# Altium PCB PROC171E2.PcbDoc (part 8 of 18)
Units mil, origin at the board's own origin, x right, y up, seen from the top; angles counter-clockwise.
Board outline 7700 x 2300 mil, 6 copper layers (Top Layer, GND 1, SIG 1, SIG 2, GND 2, Bottom Layer), stack 61.062 mil thick; 937 components, 687 nets, 11931 pads, 1719 vias.
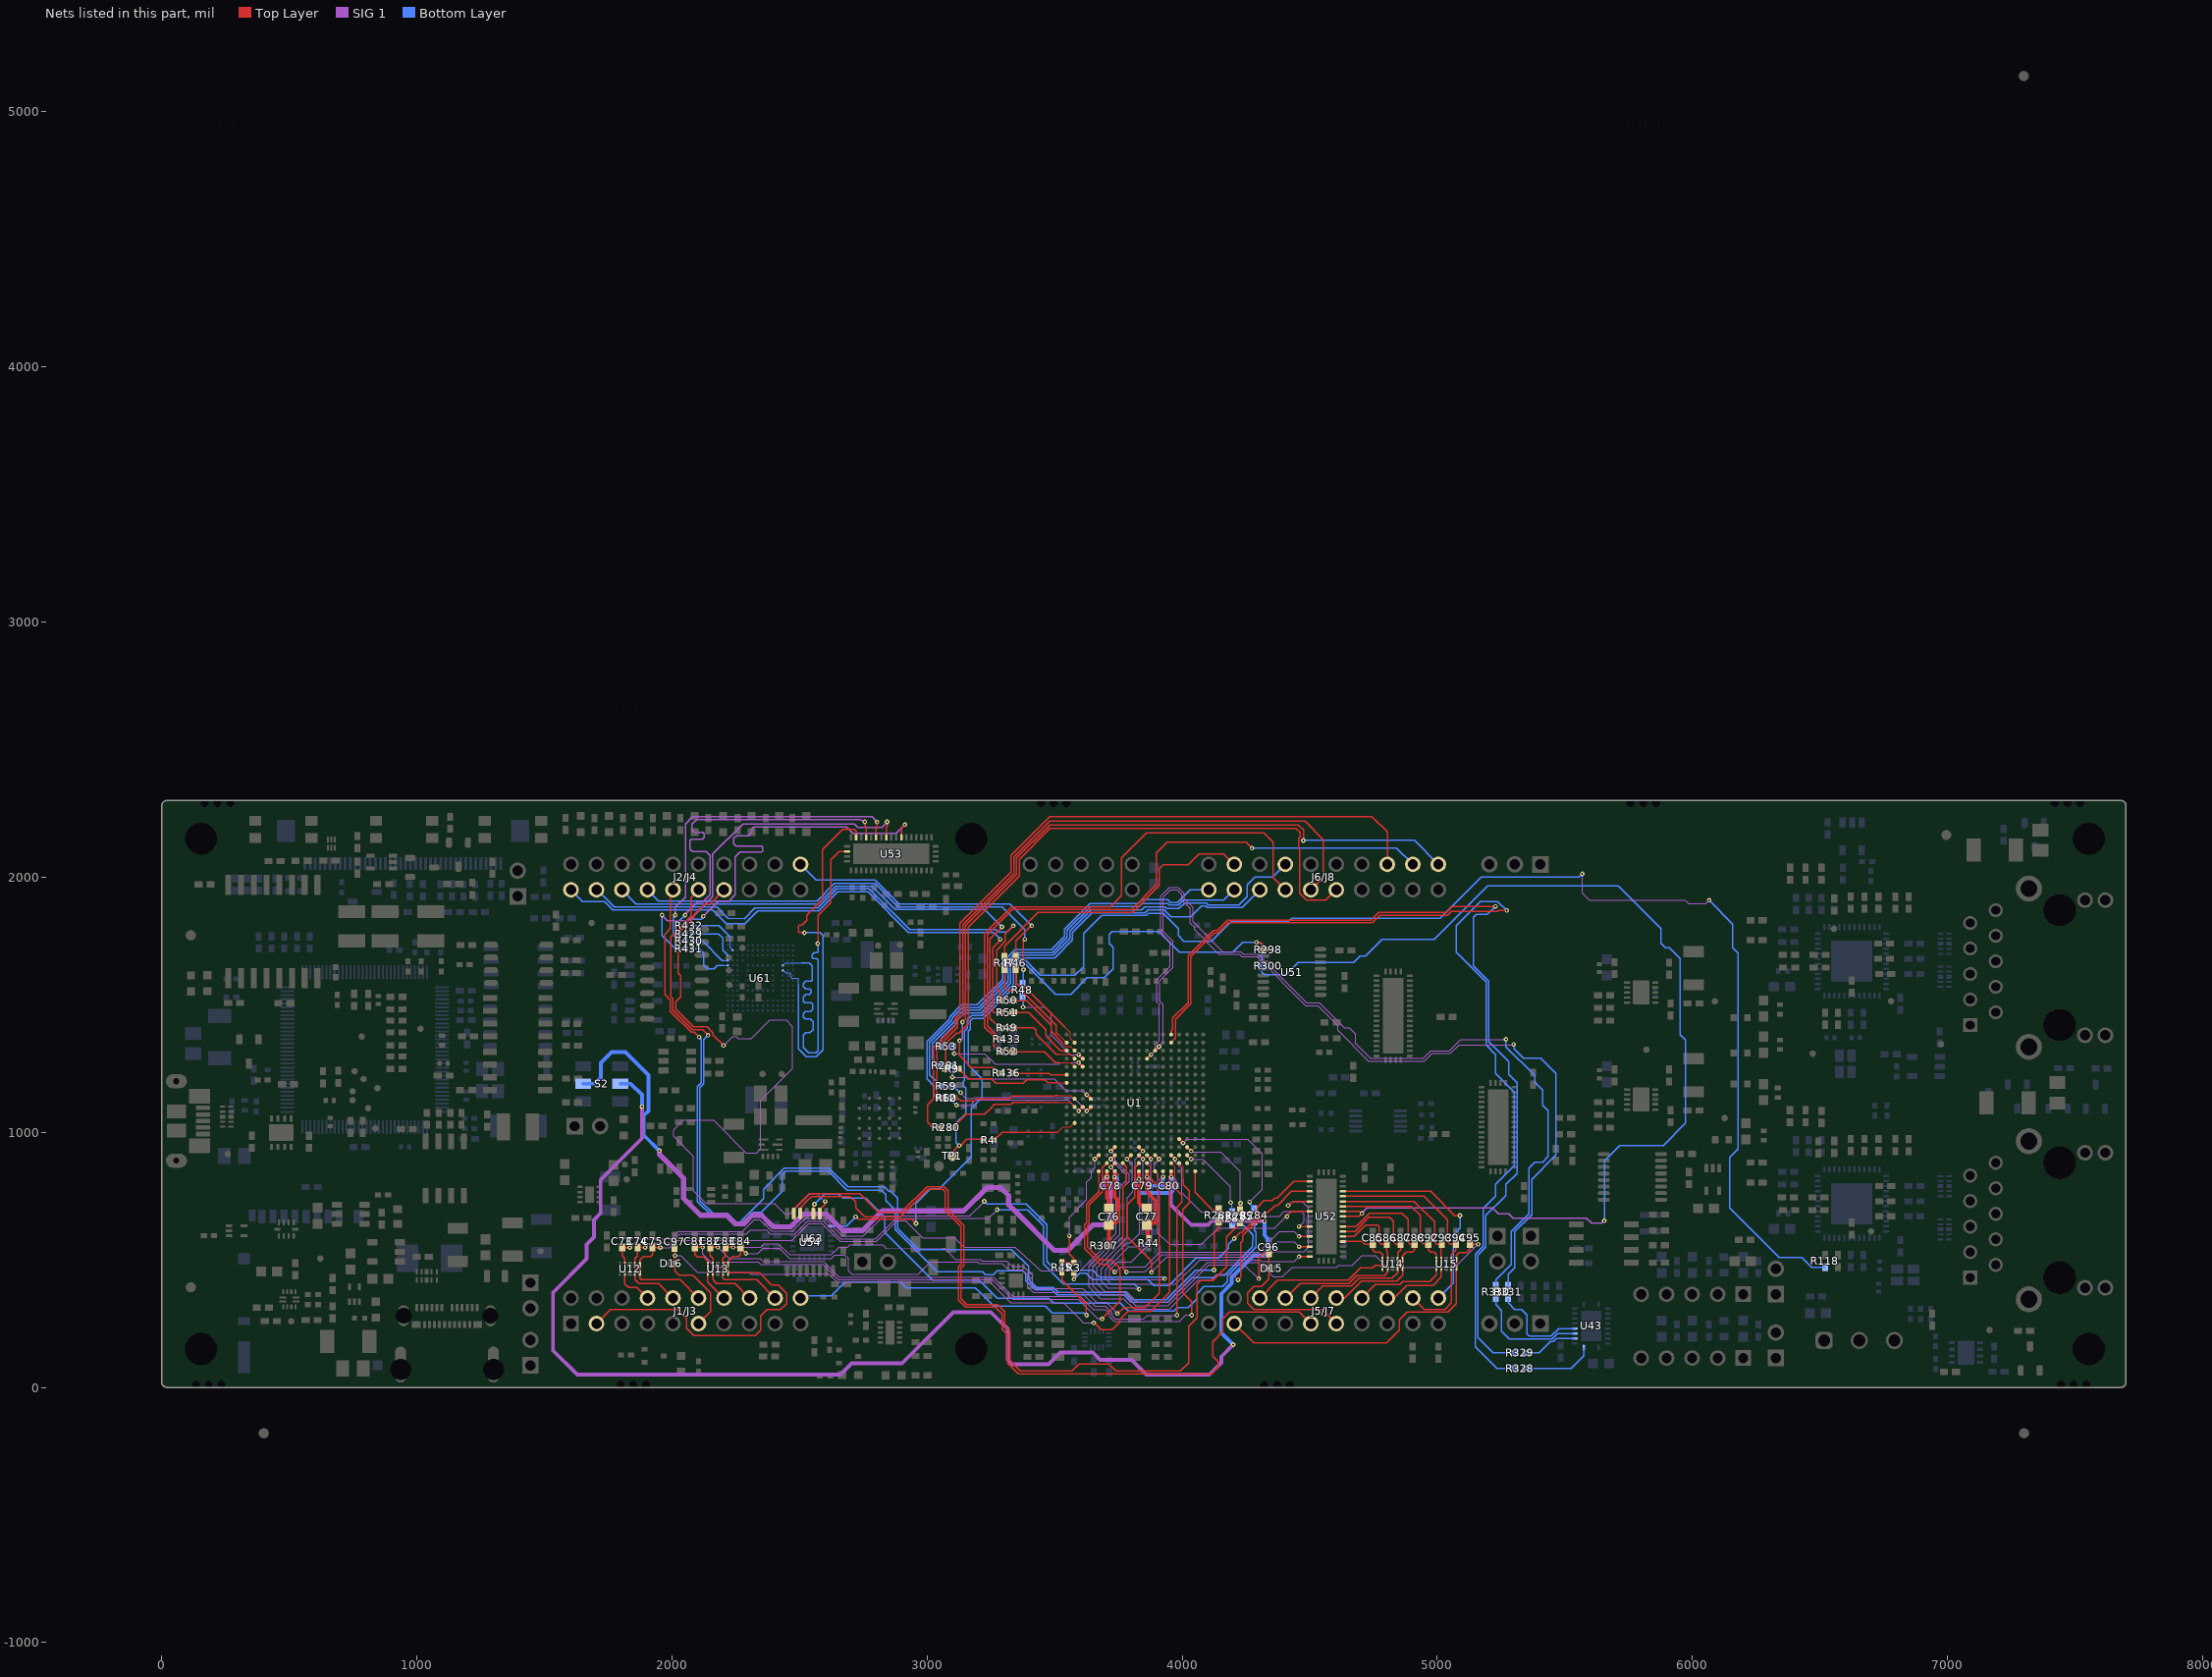
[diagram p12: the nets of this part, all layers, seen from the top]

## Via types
v1: diameter 18, hole 8, Top Layer to Bottom Layer, tented both sides, 1588 vias
v2: diameter 19.68, hole 7.87, Top Layer to Bottom Layer, tented both sides, 104 vias
v3: diameter 19.68, hole 7.87, Top Layer to Bottom Layer, 24 vias
v4: diameter 18, hole 8, Top Layer to Bottom Layer, 3 vias

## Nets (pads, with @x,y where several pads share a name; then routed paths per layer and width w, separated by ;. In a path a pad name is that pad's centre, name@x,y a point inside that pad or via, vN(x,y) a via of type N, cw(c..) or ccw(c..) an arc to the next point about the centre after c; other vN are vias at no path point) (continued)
AM263P_ADC0_AIN1: C82.1 J1/J3.28 U1.U15 U13.2 U13.9 | length 2968.2
  Top Layer w4: U1.U15@3988.08,878.86 4003.83,863.11 4003.83,815.87
  Top Layer w5.3: v1@2180,548.85 C82.1@2150,548.85 2150,516.35 2160.31,506.03 U13.9@2160.31,481.44 U13.2@2160.31,448.56 2160.31,421.62 2175,406.94 2247.24,406.94 J1/J3.28@2304.17,350 ; 4003.98,815.87 4003.98,794.2 4028.17,770.01 4028.17,723.29 4003.3,698.42 4003.3,371.19 4022.49,352.01 ; 4022.59,352.1 4037.98,336.71 4037.98,283.66 v1(4037.09,282.77)
  SIG 1 w4.75: v1(2180,548.85) 2223.8,505.05 2346.24,505.05 2357.98,493.31 2594.84,493.31 2655.35,432.81 3259.9,432.81 3335.06,357.65 3599.47,357.65 3652.12,305 3698.67,305 3716.12,287.55 3716.12,275.55 3733.57,258.1 3989.19,258.1 4014.75,283.66 4036.2,283.66 v1(4037.09,282.77)
AM263P_ADC0_AIN2: U1.T14 U52.32 | length 790.2
  Top Layer w5.3: v1(4458.39,630.63) U52.32@4500.04,630.63
  Top Layer w10: U1.T14@3956.58,910.35 v1(3972.33,894.61)
  SIG 1 w4.75: v1(3972.33,894.61) 3972.33,885.08 3999.43,857.98 3999.43,762.5 4073.08,688.86 4305.29,688.86 4323.32,670.83 4381.38,670.83 4399.8,689.25 4465.75,689.25 4477.03,677.97 4477.03,649.27 v1(4458.39,630.63)
AM263P_ADC0_AIN2_LIN1_TXD: C88.1 J5/J7.66 U14.5 U14.6 U52.7 | length 857.5
  Top Layer w5.3: J5/J7.66@4604.17,350 4635.87,350 4703.06,417.19 4841.67,417.19 4864.37,439.89 U14.5@4864.37,467.68 U14.6@4864.37,500.55 4864.37,516.12 4877.56,529.31 4902.1,529.31 4910,537.21 4910,560.42 C88.1@4911.11,561.53 4893.47,561.53 4885,570 4885,658.91 4861.58,682.33 4734.12,682.33 4682.42,630.63 U52.7@4629.96,630.63
AM263P_ADC0_AIN3: C84.1 J1/J3.2 U1.U14 U13.5 U13.6 | length 3940.1
  Top Layer w4: U1.U14@3956.58,878.86 3972.4,863.04 3972.4,816.09 3972.18,815.87
  Top Layer w5.3: J1/J3.2@1704.17,250 1759.17,305 2022.85,305 2057.7,270.15 2057.7,231.07 2085.4,203.37 2327.15,203.37 2348.22,224.45 2348.22,280.88 2372.23,304.88 2424.91,304.88 2449.05,329.02 2449.05,368.8 2416.56,401.3 2390.74,401.3 2343.48,448.56 U13.5@2219.37,448.56 U13.6@2219.37,481.44 2219.37,494.53 2238.22,513.38 2261.62,513.38 2269,520.76 C84.1@2269,544.91 ; C84.1@2269,548.85 C84.1@2269,544.91 ; v1(2289.41,525.59) 2288.33,525.59 C84.1@2269,544.91 ; 3972.18,815.87 3972.18,780.46 3999.52,753.11 3999.52,725.47 3979.46,705.41 v1(3979.46,282.66)
  SIG 1 w4.75: v1(2289.41,525.59) 2290.99,524.01 2336.11,524.01 2357.35,545.25 2420.66,545.25 2460.77,505.14 2623.82,505.14 2628.28,509.59 2638.22,519.49 2677.05,519.49 2691.97,504.56 2691.97,456.29 2705.41,442.86 2964.9,442.86 3013.89,491.85 3198.05,491.85 3203.71,486.19 3293.81,486.19 3319.1,460.9 3371.67,460.9 3395,437.57 3395,392.52 3415.02,372.5 3604.77,372.5 3658.02,319.25 3698.63,319.25 3726.17,291.71 3726.17,279.72 3737.74,268.15 3849.55,268.15 3864.06,282.66 v1(3979.46,282.66)
AM263P_ADC1_AIN0: C73.1 J1/J3.24 U1.T11 U12.2 U12.9 | length 3570.9
  Top Layer w5.3: v1(1835,548.33) C73.1@1805,548.33 1805,515.82 1815.31,505.51 1815.31,405.72 1830,391.04 1863.14,391.04 J1/J3.24@1904.17,350
  Top Layer w10: U1.T11@3862.09,910.35 v1(3877.84,894.61)
  SIG 1 w4.75: v1(1835,548.33) 1868.5,581.83 1994.64,581.83 2024.06,611.25 2276.97,611.25 2322.58,656.86 2344.56,656.86 2389.37,612.05 2472.24,612.05 2522.24,662.05 2597.23,662.05 2666.22,593.06 2750.82,593.06 2830.68,672.92 3168.08,672.92 v1(3224.39,729.23) ; v1(3877.84,894.61) 3877.84,813.9 3881.31,810.44 3881.31,571.58 3801.23,491.5 3747.49,491.5 3717.5,461.51 3717.5,460.9 3716.29,459.69 3716.29,434.28 3728.62,421.95 3928.63,421.95 v1@3931.68,425
  Bottom Layer w5.3: v1(3224.39,729.23) 3234.54,719.08 3389.14,719.08 3469.57,638.65 3469.57,493.7 3504.61,458.66 3649.62,458.66 3675.73,432.55 3870.69,432.55 3871.91,431.33 3922.81,431.33 3928.24,425.89 v1(3931.68,425.89)
AM263P_ADC1_AIN1: C83.1 J1/J3.29 U1.U11 U13.4 U13.7 | length 2801.4
  Top Layer w4: U1.U11@3862.09,878.86 3877.84,863.11 3877.84,818.36 3880.34,815.87
  Top Layer w5.3: v1@2240,548.85 C83.1@2210,548.85 2210,515.31 2199.68,505 U13.7@2199.68,481.44 U13.4@2199.68,448.56 2199.68,428.15 2205,422.84 2331.34,422.84 J1/J3.29@2404.17,350 ; v1(3745.71,289.03) 3747.34,289.03 3770.92,312.6 3854.57,312.6 3909.82,367.86 3909.82,639.65 3910.38,640.21 3910.38,785.82 3880.34,815.87
  SIG 1 w4.75: v1(2240,548.85) 2346.74,548.85 2361.27,563.38 2416.74,563.38 2460.48,519.64 2624.16,519.64 2652.71,548.19 2654.1,549.58 2687.53,549.99 ccw(c2687.48,554.74) 2690.84,551.38 2698.05,558.6 2825.99,558.6 2840.59,544 3064.19,546.12 3068.13,546.12 3069.52,544.73 3112.34,501.9 3209.15,501.9 3214.81,496.24 3311.61,496.24 3332.7,475.15 3377.57,475.15 3413.27,439.45 3413.27,400.89 3426.5,387.66 3610.31,387.66 3664.47,333.5 3702.71,333.5 3745.71,290.5 v1(3745.71,289.03)
AM263P_ADC1_AIN2: U1.T12 U52.29 | length 995.1
  Top Layer w5.3: v1(4411.13,670) 4411.13,673.36 4427.46,689.69 U52.29@4500.04,689.68
  Top Layer w10: U1.T12@3893.59,910.35 v1(3909.34,894.61)
  SIG 1 w4: 3890.46,850 3890.46,874.7 3909.34,893.58 v1(3909.34,894.61)
  SIG 1 w4.75: 3890.46,850 3904.9,835.56 3904.9,605 3949.9,560 4075.6,560 4140.36,624.76 4362.54,624.76 4407.78,670 v1(4411.13,670)
AM263P_ADC1_AIN2_SDFM0_D2: C92.1 J5/J7.67 U15.1 U15.10 U52.11 | length 926.3
  Top Layer w5.3: U52.11@4629.96,709.37 4897.79,709.37 4933.44,673.72 4933.44,574.11 4945.18,562.38 C92.1@4965,562.38 4965,540 4975,530 4988.59,530 4996.03,522.56 U15.10@4996.03,500.69 U15.1@4996.03,467.82 4996.03,440.53 4970.21,414.7 4865.21,414.7 4852.93,402.43 4756.6,402.43 J5/J7.67@4704.17,350
AM263P_ADC1_AIN3: C97.1 D16.1 J1/J3.6 U1.V12 | length 3035.3
  Top Layer w4: U1.V12@3893.59,847.36 3905,835.95 3905,822.02 3911.16,815.87
  Top Layer w5.3: C97.1@2010,547.76 2011.57,546.19 v1(2011.57,516.57) 2011.04,516.04 2011.04,490.55 2010.51,490.03 2010.51,457.6 2028.08,440.03 2082.25,440.03 2151,371.28 2151,296.83 J1/J3.6@2104.17,250 ; v1(3653.66,252.52) 3655.84,252.52 3682.98,225.39 3724.72,225.39 3754.74,255.41 3754.74,264.98 3787.78,298.02 3876.43,298.02 3951.58,373.17 3951.58,775.44 3911.16,815.87
  SIG 1 w4.75: v1(2011.57,516.57) 2034.76,516.57 2099.66,451.68 2302.03,451.68 2309.45,444.26 2460.97,444.26 2462.46,445.76 2613.97,445.76 2647.02,412.71 3247,412.71 3327.71,332 3534.6,332 3595.72,270.88 3595.72,270.44 3612.88,253.28 3652.9,253.28 v1(3653.66,252.52)
AM263P_ADC2_AIN0: C74.1 J1/J3.25 U1.R10 U12.4 U12.7 | length 3407.6
  Top Layer w5.3: v1(1895,548.33) C74.1@1865,548.33 1865,514.79 1854.68,504.48 U12.7@1854.68,480.91 U12.4@1854.68,448.04 1854.68,422.25 1870,406.94 1947.24,406.94 J1/J3.25@2004.17,350
  Top Layer w10: U1.R10@3830.6,941.85 v1(3846.35,926.1)
  SIG 1 w4.75: v1(1895,548.33) 1914.25,567.58 1995.86,567.58 2029.49,601.2 2291.98,601.2 2307.39,616.62 2370.59,616.62 2385.21,602 2481.74,602 2531.74,652 2593.07,652 2606.85,638.22 2662.06,583.01 2797.84,583.01 2818.52,603.69 2818.57,603.74 2879.32,662.87 3241.32,662.87 v1(3274.95,696.5) ; v1(3831.58,385.13) 3817.01,385.13 3811.63,390.5 3708.44,390.5 3682.23,416.7 3682.23,464.48 3783.89,566.14 3796.1,566.14 3832.75,602.79 3832.75,778.4 3815,796.15 3815,894.76 v1(3846.35,926.1)
  Bottom Layer w5.3: v1(3274.95,696.5) 3393.99,696.5 3455.71,634.78 3455.71,484.14 3535.57,404.28 3812.43,404.28 v1(3831.58,385.13)
AM263P_ADC2_AIN1: U1.T10 U52.38 | length 1460.2
  Top Layer w5.3: v1(4458.39,512.52) U52.38@4500.04,512.52
  Top Layer w10: U1.T10@3830.6,910.35 v1(3846.35,894.61)
  SIG 1 w4: v1(3846.35,894.61) 3847,893.95 3847,815.87
  SIG 1 w4.75: 3847,815.87 3847,799.35 3870.75,775.6 3870.75,579.71 3842.93,551.89 3791.41,551.89 3700.43,460.9 3700.43,426.71 3722.38,404.75 3825.52,404.75 3825.89,404.38 3973.87,404.38 4069.46,499.96 4303.16,499.96 4309.85,493.27 4439.14,493.27 v1(4458.39,512.52)
AM263P_ADC2_AIN1_MCAN5_RX: C85.1 J5/J7.63 U14.1 U14.10 U52.4 | length 781.9
  Top Layer w5.3: J5/J7.63@4304.17,350 4374.17,420 4650.72,420 4698.4,467.68 4746.98,467.68 4756.74,477.44 4772.92,477.44 4774.55,475.8 4784.34,475.8 4784.34,468.97 U14.1@4785.63,467.68 ; U52.4@4629.96,571.57 4705.59,571.57 4715.63,561.53 C85.1@4747.11,561.53 4747.11,538.93 4755.01,531.03 4774.59,531.03 4785.63,519.99 U14.10@4785.63,500.55 U14.1@4785.63,470.66
AM263P_ADC2_AIN2: U1.U10 U52.27 | length 1484.3
  Top Layer w5.3: U1.U10@3830.6,878.86 3813.63,861.89 3813.63,815.87 3813.63,745.2 3785.48,717.06 3785.48,589.52 3880,495 v1(3880,450.85) ; v1(4415.63,712.91) 4416.63,712.91 4432.77,729.06 U52.27@4500.04,729.06
  SIG 1 w4.75: v1(3880,450.85) 3939.16,510.01 4335.27,510.01 4357.02,531.77 4477.64,531.77 4495.75,549.88 4495.75,703.31 4470,729.06 4432.77,729.06 4429.21,725.5 v1(4415.63,712.91)
AM263P_ADC2_AIN2_SDFM0_CLK2: C93.1 J5/J7.68 U15.2 U15.9 U52.12 | length 879.5
  Top Layer w5.3: U52.12@4629.96,729.06 4909.46,729.06 4990,648.51 4990,570 4998.33,561.67 C93.1@5017.97,561.67 5015.48,559.18 5015.48,500.94 U15.9@5015.72,500.69 U15.2@5015.72,467.82 5015.72,432.26 4983.46,400 4879.37,400 4829.37,350 J5/J7.68@4804.17,350
AM263P_ADC2_AIN3: C95.1 J5/J7.42 U1.T9 U15.5 U15.6 | length 3575.6
  Top Layer w5.3: J5/J7.42@4204.17,250 4280.97,173.2 4801.74,173.2 4852.06,223.52 4852.06,265 4881.8,294.74 5041.07,294.74 5074.77,328.45 U15.5@5074.77,467.82 U15.6@5074.77,500.69 5074.77,517.29 5085.81,528.33 5114.41,528.33 5128.54,542.46 C95.1@5128.54,561.67 5144.64,561.67 v1(5159.85,561.03)
  Top Layer w10: v1(3783.35,894.61) U1.T9@3799.1,910.35
  SIG 1 w4.75: v1(3783.35,894.61) 3804.95,873.01 3804.95,791.99 3806.82,790.12 3806.82,766.43 3785,744.61 3785,587.4 3665.68,468.08 3665.68,406.97 3696.4,376.25 3781.88,376.25 3823.5,334.63 3943.14,334.63 4098.43,489.91 4299,489.91 4355.75,433.16 4393.5,433.16 4431.09,470.75 4604.29,470.75 4611.68,478.14 4666.51,478.14 4704.94,516.57 4756.24,516.57 4802.06,470.75 5069.57,470.75 v1(5159.85,561.03)
AM263P_ADC3_AIN0: C75.1 J1/J3.26 U1.U7 U12.5 U12.6 | length 2776.5
  Top Layer w5.3: v1(1954,548.33) C75.1@1924,548.33 1924,520.24 1916.62,512.86 1887.02,512.86 1874.37,500.2 U12.6@1874.37,480.91 U12.5@1874.37,448.04 1874.37,428.47 1880,422.84 2031.34,422.84 J1/J3.26@2104.17,350
  Top Layer w10: v1(3720.36,863.11) U1.U7@3736.11,878.86
  SIG 1 w4: v1@3720.36,862.49 v1(3720.36,863.11)
  SIG 1 w4.75: v1(1954,548.33) 1990.82,548.33 2017.38,574.89 2018.77,576.28 2022.71,576.28 2324.7,576.22 2470.17,576.22 2535.9,641.95 2588.9,641.95 2596.8,634.06 2659.07,571.78 2802.45,571.78 2883.49,652.82 2914.87,652.82 2982.68,585.01 3108.65,585.01 3143.55,550.11 3344.44,550.11 3447.34,457.66 3600.73,457.66 3695.11,552.04 3741.83,604.69 3741.83,786.42 3750.08,794.67 3750.08,832.77 v1@3720.36,862.49
AM263P_ADC3_AIN1: U1.U8 U52.36 | length 1219.8
  Top Layer w5.3: U1.U8@3767.61,878.86 3782.13,864.33 3782.13,815.87 3782.13,798.59 3768.05,784.5 3768.05,465.99 3781.85,452.18 v1(3781.85,452.07) ; v1(4458.39,551.89) U52.36@4500.04,551.89
  SIG 1 w4.75: v1(3781.85,452.07) 3782.53,452.75 3854.68,452.75 3921.99,520.06 4320.06,520.06 4371.14,571.14 4439.14,571.14 v1(4458.39,551.89)
AM263P_ADC3_AIN1_MCAN5_TX: C86.1 J5/J7.64 U14.2 U14.9 U52.5 | length 812.1
  Top Layer w5.3: J5/J7.64@4404.17,350 4462.03,407.86 4653.57,407.86 4684.1,438.39 4792.53,438.39 4805.31,451.17 U14.2@4805.31,467.68 U14.9@4805.31,500.55 4805.31,533.2 4802.11,536.4 C86.1@4802.11,561.53 4780.42,561.53 4772.38,569.58 4772.38,630 4765.84,636.54 4719.02,636.54 4673.74,591.26 U52.5@4629.96,591.26
AM263P_ADC3_AIN2: U1.T7 U52.25 | length 1814.2
  Top Layer w5.3: v1(4219.1,420.96) 4229.38,431.24 4229.38,566.34 4237.5,574.46 4237.5,595.21 4325.55,683.26 4333.87,683.26 4364,713.38 4373.5,713.38 4428.54,768.43 U52.25@4500.04,768.43
  Top Layer w10: v1(3720.36,894.61) U1.T7@3736.11,910.35
  SIG 1 w4.75: v1(3720.36,894.61) 3720.36,893.05 3781.11,832.3 3781.11,811.39 3756.08,786.36 3756.08,598.79 3634.41,477.12 3634.41,392.96 3679.62,347.75 3770.07,347.75 3811.7,306.13 3949.9,306.13 3985.7,341.93 3985.7,344.21 4061.38,419.89 4063.66,419.89 4063.7,419.93 4114.37,419.93 4137.91,443.48 4196.59,443.48 v1(4219.1,420.96)
AM263P_ADC3_AIN2_SDFM0_D3: C94.1 J5/J7.69 U15.4 U15.7 U52.13 | length 987.1
  Top Layer w5.3: U52.13@4629.96,748.74 4948.18,748.74 5040.31,656.61 5040.31,573.23 5051.87,561.67 C94.1@5073,561.67 5073,538 5055.09,520.09 U15.7@5055.09,500.69 U15.4@5055.09,467.82 5055.09,331.25 5029.53,305.69 4948.48,305.69 J5/J7.69@4904.17,350
AM263P_ADC3_AIN3: C96.1 D15.2 J5/J7.46 U1.R7 | length 2166.5
  Top Layer w5.3: v1(4300.31,425.72) 4300.31,508.74 4317.89,526.31 C96.1@4339.72,526.31 4339.72,467.6 D15.2@4338.78,466.66 4338.78,423.78 4310,395 4282.16,395 4257.41,370.25 4257.41,329.77 4281.66,305.53 4548.64,305.53 J5/J7.46@4604.17,250
  Top Layer w10: v1(3720.36,926.1) U1.R7@3736.11,941.85
  SIG 1 w4: v1(3720.36,926.1) 3736.86,909.61 3736.86,888.39 3791.97,833.28 3791.97,815.87 3791.97,808.04
  SIG 1 w4.75: 3791.97,808.04 3768.32,784.39 3768.32,590.88 3650,472.55 3650,397.52 3685.52,362 3775.98,362 3817.6,320.38 3944.27,320.38 4103.76,479.86 4244.07,479.86 4298.21,425.72 v1(4300.31,425.72)
AM263P_ADC4_AIN0: C81.1 J1/J3.27 U1.U6 U13.1 U13.10 | length 2754.9
  Top Layer w5.3: v1@2120,548.85 C81.1@2090,548.85 2090,520 2098.65,511.35 2124.65,511.35 2140.63,495.36 U13.10@2140.63,481.44 U13.1@2140.63,448.56 2140.63,413.54 J1/J3.27@2204.17,350 ; v1(3686.04,268.25) 3755.86,338.08 3755.86,466.58 3722.44,500 3679.58,500 3629.29,550.3 3629.29,634.29 3635.93,640.93 3635.93,714.5 3687.64,766.21 3687.64,861.89 U1.U6@3704.61,878.86
  SIG 1 w4.75: v1(2120,548.85) 2120,522.52 2171.32,471.2 2189.57,471.2 2210.78,492.41 2337.74,492.41 2347.39,482.76 2591.19,482.76 2651.18,422.76 3255.74,422.76 3334,344.5 3593.25,344.5 3667.54,270.21 3684.08,270.21 v1(3686.04,268.25)
AM263P_ADC4_AIN1: U1.V5 U52.34 | length 1318.8
  Top Layer w5.3: U1.V5@3673.12,847.36 3673.12,766.68 3625.33,718.89 3625.33,645.32 3618.69,638.68 3618.69,544.2 3680.24,482.64 3704.97,482.64 v1(3735.54,452.07) ; v1(4458.39,591.26) U52.34@4500.04,591.26
  SIG 1 w4.75: v1(3735.54,452.07) 3738.97,452.07 3758.61,471.71 3853.48,471.71 3911.89,530.11 4301.1,530.11 4381.49,610.51 4439.14,610.51 v1(4458.39,591.26)
AM263P_ADC4_AIN1_LIN1_RXD: C87.1 J5/J7.65 U14.4 U14.7 U52.6 | length 837
  Top Layer w5.3: J5/J7.65@4504.17,350 4551.43,397.26 4662,397.26 4692.53,427.79 4822.45,427.79 4844.69,450.03 U14.4@4844.69,467.68 U14.7@4844.69,500.55 4844.69,527.99 4856.7,540 C87.1@4856.7,561.53 4838.47,561.53 4827.2,572.8 4827.2,651.1 4812.48,665.82 4732.61,665.82 4677.73,610.94 U52.6@4629.96,610.94
AM263P_ADC_CAL0: U1.U16
AM263P_ADC_CAL1: U1.T15
AM263P_ADC_VREFHI_G01: C77.1 C79.1 C80.1 S2.2 U1.V10 U1.V14 | length 5890.2
  Top Layer w15: U1.V10@3830.6,847.36 3831.11,846.85 v1(3831.11,816.77) 3831.11,810.33 3830.6,809.82 3830.6,723.99 3841.97,712.62 3850.13,712.62 3853.51,709.23 C77.1@3853.51,701.07 ; v1(3956.58,825) U1.V14@3956.58,847.36
  SIG 1 w15: v1(1882.41,1100.31) 1882.41,976.67 1720.31,814.58 1720.31,682.87 1693.67,656.23 1693.67,588.24 1665.77,560.34 1665.77,503.94 1533.7,371.86 1533.7,144.46 1628.33,49.82 2659.82,49.82 2704.28,94.28 2901.88,94.28 3102.37,294.78 3250,294.78 3316.5,228.28 3316.5,109.16 3334.64,91.02 3476.28,91.02 3521.46,136.2 3650.62,136.2 3679.07,107.75 3801.6,107.75 3859.39,49.96 4106.67,49.96 4153.1,96.38 4153.1,120.31 v1(4200.1,167.31) ; v1(3956.58,825) 3956.01,824.43 3956.01,822.3 3955.63,821.92 3955.63,719.49 3956.05,719.06 3956.05,716.42 4035.38,637.09 4101.11,637.09 4115.3,651.28 v1(4322.35,651.28)
  Bottom Layer w15: S2.2@1797.54,1190 1839.19,1190 1882.41,1146.78 v1(1882.41,1100.31) ; v1(3831.11,816.77) 3823.14,808.8 3823.14,789.94 3825.13,789.94 3829.44,785.63 3829.44,771.54 3838.22,762.75 3955.21,762.75 3964,771.54 3964,785.63 3968.31,789.94 C80.1@3972.24,789.94 3972.24,809.34 v1(3956.58,825) ; v1(4200.1,167.31) 4153.43,213.98 4153.43,366.44 4194.73,407.74 4194.73,431.06 4281.19,517.53 4317.53,517.53 4334.93,534.93 4334.93,583.65 4322.35,596.23 v1(4322.35,651.28)
AM263P_ADC_VREFHI_G2: C76.1 C78.1 S2.5 U1.V6 | length 3332.8
  Top Layer w15: U1.V6@3704.61,847.36 v1(3704.61,825) 3704.61,742.32 3713.32,733.62 3713.32,698.14 C76.1@3713.17,698
  SIG 1 w8: 3704.49,800.8 3707.05,798.24 ; v1@3704.49,824.87 v1(3704.61,825)
  SIG 1 w20: v1(1950.75,927.95) 1950.75,914.12 2045.27,819.6 2045.27,741.3 2112.03,674.54 2214.47,674.54 2247.99,641.02 2281.74,641.02 2315.26,674.54 2351.88,674.54 2396.69,629.72 2464.91,629.72 2514.92,679.72 2604.55,679.72 2669.63,614.64 2747.41,614.64 2824.25,691.49 3143.74,691.49 3235.35,783.1 3288,783.1 3319.47,751.63 3319.47,716.29 3349.15,686.61 3498.56,537.2 3550.76,537.2 3650.66,637.09 3700.33,637.09 3715.62,652.38 3715.62,789.67 3707.05,798.24 ; 3704.49,800.8 v1@3704.49,824.87
  Bottom Layer w15: S2.5@1651.87,1190 1697.96,1190 1721.8,1213.85 1721.8,1272.05 1763.82,1314.08 1816.93,1314.08 1907.31,1223.69 1907.31,1083.75 1889.85,1066.3 1889.85,988.19 v1@1950.09,927.95 ; C78.1@3696.74,789.94 3696.74,817.13 v1(3704.61,825)
AM263P_ADC_VREFLO_G01: C77.2 C79.2 C80.2 R44.2 U1.V11 U1.V13 | length 450
  Top Layer w4: v1(3925.09,825) U1.V13@3925.09,847.36
  Top Layer w15: C77.2@3861.07,637.7 3868.69,645.32 3893.65,645.32 3894.93,646.6 3894.93,733.21 3862.67,765.48 3862.67,815.87 3862.67,824.43 v1(3862.09,825) U1.V11@3862.09,847.36 ; C77.2@3864.29,628.58 3864.29,597.52 3867.19,594.61 3867.19,586.76 R44.2@3869.54,584.42
  Bottom Layer w15: v1(3862.09,825) 3862.09,824.19 3868.43,817.85 C79.2@3868.43,789.94 C80.2@3925,789.94 3925,824.91 v1(3925.09,825)
AM263P_ADC_VREFLO_G2: C76.2 C78.2 R307.2 U1.V7 | length 362.7
  Top Layer w15: R307.2@3713.62,555 3713.17,555.45 3713.17,635.99 3724.37,647.19 3740.05,647.19 3748.83,655.98 3748.83,733.91 3734.71,748.04 3734.71,815.87 3734.71,825.81 3736.11,827.21 U1.V7@3736.11,847.36
  Bottom Layer w15: v1(3734.71,825) 3735.28,824.43 3736.68,824.43 3743.98,817.13 C78.2@3743.98,789.94
AM263P_BP_MUX_SEL: R298.2 R300.2 U51.1 U52.9 U52.10 U63.7 | length 7396.9
  Top Layer w5.3: v1(2720.04,668.83) 2730.64,658.23 2940.7,658.23 v1(2956.41,642.55) ; v1(4291.03,1744.24) 4306.84,1744.24 4317.8,1733.28 U51.1@4317.8,1717.48 ; U52.9@4629.96,670 4693.01,670 v1(4705,681.99) 4697.31,689.68 U52.10@4629.96,689.68
  SIG 1 w5.3: v1(4705,681.99) v1@4705.75,682.74 ; v1@4705.15,683.35 4725.13,703.33 5215.87,703.33 5239.16,680.04 5281.04,680.04 5298,663.08 5585.13,663.08 5605.21,643 5644.31,643 v1(5654.39,653.09)
  Bottom Layer w5.3: U63.7@2623.77,632.69 2683.9,632.69 v1(2720.04,668.83) ; v1@2956.39,642.57 2956.39,720.88 3011.71,776.2 3045.69,776.2 3173.69,904.21 3173.69,1094.74 3192.9,1113.95 3192.9,1114.06 3204.33,1125.49 3204.44,1125.49 3215.19,1136.24 3215.19,1209.93 3197.95,1227.17 ; 3197.82,1227.05 3161.21,1263.66 3161.21,1396.25 3169.22,1404.26 3169.22,1436.23 3179.91,1446.92 3219.93,1446.92 3348.77,1575.76 3348.77,1644.44 3366.83,1662.51 3382.13,1662.51 3503.4,1541.24 3562.92,1541.24 3627.8,1606.12 3694.35,1606.12 3729.57,1641.35 3729.57,1724.32 3713.62,1740.28 3713.62,1775.16 3725.58,1787.12 3909.07,1787.12 3989.71,1706.48 4199.68,1706.48 4237.44,1744.24 v1(4291.03,1744.24) 4291.19,1744.08 4302.68,1744.08 4312.89,1733.88 R300.2@4312.89,1652.52 4312.89,1626.91 4323,1616.79 4405.75,1616.79 4453.96,1665 4672.04,1665 4697.54,1690.5 4717.5,1690.5 4783.54,1756.54 4988.39,1756.54 5197.32,1965.47 5710.03,1965.47 5876.5,1799 5876.5,1741.5 5894,1724 5908.74,1724 5951,1681.74 5951,1383.57 5972.85,1361.72 5972.85,1035.35 5885.7,948.2 5714.61,948.2 5655,888.59 5655,653.69 v1(5654.39,653.09)
AM263P_CLKOUT0: R4.2 R118.1 TP1.1 | length 5932.9
  Top Layer w5.3: TP1.1@3099.06,906.94 3105.3,913.18 3105.3,929.18 3126.31,950.19 3134.53,950.19 3142.67,958.33 3156.79,972.45 3217.83,972.45 R4.2@3221.22,969.06
  SIG 1 w4.75: v1(5568.36,2012.89) 5568.36,1937.74 5596.85,1909.25 5970.75,1909.25 5984.25,1895.75 6051.33,1895.75 v1(6065,1909.42)
  Bottom Layer w5.3: v1(3126.08,947.76) 3114.14,959.7 3114.14,1035.32 3151.1,1072.28 3151.1,1172.52 3141.87,1181.75 3141.87,1197.92 3146.71,1202.76 3146.71,1396.74 3158.48,1408.5 3158.48,1440.98 3175.02,1457.52 3215.54,1457.52 3338.17,1580.15 3338.17,1648.83 3362.44,1673.11 3386.52,1673.11 3444.63,1615 3580,1615 3613.9,1648.9 3613.9,1778.89 3684.53,1849.52 3858.86,1849.52 3867.49,1858.15 3925.03,1858.15 3985,1798.18 3985,1771.15 4007.27,1748.88 4114.83,1748.88 4190.89,1824.93 4415.03,1824.93 4429.02,1838.92 5010.58,1838.92 5172.52,2000.87 5556.33,2000.87 v1(5568.36,2012.89) ; v1(6065,1909.42) 6157.91,1816.51 6157.91,1723.92 6179.31,1702.52 6179.31,934.87 6146.9,902.46 6146.9,703.11 6340.09,509.92 6428.75,509.92 6467.3,471.38 R118.1@6520,471.38
AM263P_CLKOUT0_R: R4.1 U1.M2 | length 345.9
  Top Layer w4: 3515.64,1002.84 3533.39,1020.59 3562.88,1020.59 U1.M2@3578.63,1036.34
  Top Layer w5.3: R4.1@3260.59,969.06 3262.56,969.06 3293.6,1000.11 3512.9,1000.11 3515.64,1002.84
AM263P_DAC_OUT1: J1/J3.30 R45.1 | length 1408.7
  Top Layer w5.3: R45.1@3528.72,450.24 3528.72,420.58 3623,326.29 3623,284.59 v1(3625.02,282.58)
  Bottom Layer w5.3: J1/J3.30@2504.17,350 2517.07,350 2525.78,358.71 2624.66,358.71 2679.17,413.22 2895.74,413.22 2919.48,389.48 3189.56,389.48 3205.31,373.73 3205.43,373.73 3261.18,317.98 3464.43,317.98 3490.91,291.5 3615.56,291.5 3624.49,282.58 v1(3625.02,282.58)
AM263P_DAC_OUT2: R3.1 U52.23 | length 1179.9
  Top Layer w5.3: R3.1@3575.19,448.84 3575.59,448.44 v1(3575.59,423.8) ; v1(4204.17,583.26) 4227.69,606.78 4234.08,606.78 4294.17,666.87 4294.17,705.98 4319.99,731.8 4352.43,731.8 4362.41,741.77 4371.91,741.77 4437.93,807.8 U52.23@4500.04,807.8
  Bottom Layer w5.3: v1(3575.59,423.8) 3598.94,447.15 3623.25,447.15 3648.44,421.95 3866.3,421.95 3888.78,399.46 3948.02,399.46 4054.9,506.35 4142.26,506.35 4182.08,546.17 4182.08,561.18 v1(4204.17,583.26)
AM263P_DAC_OUT2_SDFM0_CLK3: J5/J7.70 U52.14 | length 859
  Top Layer w5.3: U52.14@4629.96,768.43 4973.69,768.43 5069.14,672.97 5087.95,672.97 v1(5088.74,673.76)
  Bottom Layer w5.3: J5/J7.70@5004.17,350 5063.33,409.15 5063.33,597.03 5090.66,624.36 5090.66,671.83 v1(5088.74,673.76)
AM263P_DAC_OUT_R: R3.2 R45.2 U1.T5 | length 523.2
  Top Layer w5.3: R45.2@3528.72,489.61 3573.8,489.61 R3.2@3574.55,488.85 ; v1(3557.81,594.15) 3557.81,521.62 3574.55,504.87 R3.2@3574.55,488.85 ; R3.2@3575.19,488.21 R3.2@3574.55,488.85
  Top Layer w10: v1(3657.37,894.61) U1.T5@3673.12,910.35
  SIG 1 w4: 3636.96,815.87 3645,823.91 3645,848.34 3657.37,860.71 v1(3657.37,894.61)
  SIG 1 w4.75: v1(3557.81,594.15) 3557.81,667.03 3626.32,735.54 3626.32,805.23 3636.96,815.87
AM263P_EMMC0_CLK_MUX: U53.40 U61.M5 | length 1573.6
  Top Layer w5.3: v1(2571.22,1739.68) 2573.03,1741.49 2573.03,1850.25 2622.73,1899.94 2622.73,2067.48 2656.13,2100.88 U53.40@2686.56,2100.88
  Bottom Layer w3.4: U61.M5@2434.92,1654.01 2441.81,1660.91 ; 2441.9,1660.82 2444.91,1663.84 2507.2,1663.84 2508.01,1663.03
  Bottom Layer w5.3: 2508.01,1663.77 2538.54,1663.77 2549.68,1652.63 2549.68,1595.66 2545.97,1591.95 2523.93,1591.95 2515.62,1583.65 2515.62,1570.62 2523.76,1562.48 2540.29,1562.48 2546.85,1555.93 2546.85,1547.44 2540.45,1541.04 2525.35,1541.04 2515.62,1531.32 2515.62,1514.38 2521.81,1508.19 2544.98,1508.19 2551.21,1501.96 2551.21,1481.05 2542.67,1472.51 2522.88,1472.51 2515.62,1465.26 2515.62,1451.41 2523.33,1443.7 2542.3,1443.7 2552.83,1433.16 2552.83,1402.76 2540.64,1390.57 2524.86,1390.57 2515.62,1381.33 2515.62,1331.69 2536.8,1310.52 2564.39,1310.52 2573.03,1319.16 2573.03,1674.92 2567.28,1680.68 2554.27,1680.68 2549.98,1684.97 2549.98,1697.11 2556.63,1703.76 2568.77,1703.76 2573.03,1708.03 2573.03,1737.87 v1(2571.22,1739.68)
AM263P_EMMC0_CMD_MUX: U53.37 U61.M6 | length 1580.7
  Top Layer w5.3: v1(2519.19,1782.19) 2499.54,1782.19 2495.38,1786.35 2495.38,1808.38 2498.48,1811.49 2509.14,1811.49 2528.12,1830.46 2528.12,1850.31 2590.93,1913.12 2590.93,2107.74 2669.77,2186.59 2714.68,2186.59 2721.99,2179.27 U53.37@2721.99,2156
  Bottom Layer w3.4: U61.M6@2435.29,1634.18 2444.97,1624.5 2460.46,1624.5 2464.47,1620.49 ; 2464.43,1620.49 2464.43,1610.75 2464.46,1610.71 2464.46,1610.57 2470.22,1604.82 2491.53,1604.82 2496.52,1599.82 2496.52,1578
  Bottom Layer w5.3: 2496.52,1578 2496.52,1327.39 2527.57,1296.35 2565.21,1296.35 2591.82,1322.96 2591.82,1770.53 2580.17,1782.19 v1(2519.19,1782.19)
AM263P_EMMC0_D0: R429.1 U61.A3 | length 204.6
  Bottom Layer w5.3: R429.1@2076.59,1776.94 2182.95,1776.94 2198.63,1761.25 2198.63,1714.22 2218.38,1694.48 U61.A3@2218.38,1693.38
AM263P_EMMC0_D0_MUX: R429.2 U53.35 | length 1416.5
  Top Layer w5.3: v1@2756.13,2216.63 2758.2,2214.56 2758.2,2199.92 2761.36,2196.76 U53.35@2761.36,2156
  SIG 1 w5.3: v1(2051.87,1851.18) 2051.87,1854.41 2100.05,1902.59 2121.44,1902.59 2149.2,1930.35 2149.2,2084.53 2133.73,2100 2081.13,2100 2070.87,2110.26 2070.87,2143.34 2076.78,2149.25 2118.92,2149.25 2126.5,2156.83 2126.5,2169.06 2120.71,2174.84 2088.59,2174.84 2078.72,2184.71 2078.72,2207.57 2096.7,2225.55 2740.5,2225.55 2747,2219.06 2753.7,2219.06 v1@2756.13,2216.63
  Bottom Layer w5.3: v1(2051.87,1851.18) 2028.95,1828.26 2028.95,1785.4 2037.41,1776.94 R429.2@2056.51,1776.94
  other v1: 2755.72,2216.63
AM263P_EMMC0_D1: R430.1 U61.A4 | length 173.1
  Bottom Layer w3.4: 2204.66,1673.7 U61.A4@2218.38,1673.7
  Bottom Layer w5.3: R430.1@2076.59,1749.33 2120.2,1749.33 2195.84,1673.7 2204.66,1673.7
AM263P_EMMC0_D1_MUX: R430.2 U53.33 | length 1351.5
  Top Layer w5.3: U53.33@2800.73,2156 2800.73,2190.36 2804.26,2193.89 v1@2804.26,2216.62
  SIG 1 w5.3: v1@2013.35,1849.94 2013.35,1882.68 2052.88,1922.2 2052.88,2208.34 2080.69,2236.15 2784.6,2236.15 2804.26,2216.49 v1(2804.26,2215.39)
  Bottom Layer w5.3: v1(2013.35,1851.18) 2005.33,1843.15 2005.33,1773.06 2029.06,1749.33 R430.2@2056.51,1749.33
AM263P_EMMC0_D2: R431.1 U61.A5 | length 208.4
  Bottom Layer w3.4: 2201.3,1654.01 U61.A5@2218.38,1654.01
  Bottom Layer w5.3: R431.1@2076.59,1719.72 2107.64,1719.72 2125,1702.37 2125,1654.55 2139.29,1640.25 2164.28,1640.25 2178.04,1654.01 2201.3,1654.01
AM263P_EMMC0_D2_MUX: R431.2 U53.31 | length 1420.7
  Top Layer w5.3: U53.31@2840.1,2156 2840.1,2197.03 2843.3,2200.23 v1(2843.3,2216.63)
  SIG 1 w5.3: v1(1960.83,1851.18) 1982.17,1829.84 2066.02,1829.84 2159.8,1923.62 2159.8,2090.63 2278.18,2209.02 2714.89,2209.02 2729.36,2194.55 2822.4,2194.55 2843.3,2215.45 v1(2843.3,2216.63)
  Bottom Layer w5.3: v1(1960.83,1851.18) 1960.83,1771.62 2012.73,1719.72 R431.2@2056.51,1719.72
AM263P_EMMC0_D3: R432.1 U61.B2 | length 226.7
  Bottom Layer w3.4: 2228.53,1765.41 2228.2,1765.09 2228.2,1722.93 U61.B2@2238.07,1713.07
  Bottom Layer w5.3: R432.1@2076.59,1810.15 2183.49,1810.15 2228.22,1765.41
AM263P_EMMC0_D3_MUX: R432.2 U53.28 | length 1454.2
  Top Layer w5.3: U53.28@2899.16,2156 2899.22,2156.06 2899.22,2179.04 ; 2899.24,2179.06 2899.24,2191.91 v1(2913.24,2205.91)
  SIG 1 w5.3: v1(2122.97,1846.47) 2180.73,1904.23 2222.64,1904.23 2248.52,1930.11 2248.52,2079.98 2266.04,2097.5 2351.81,2097.5 2354.92,2100.6 2354.92,2118.44 2351.81,2121.55 2251.16,2121.55 2241.58,2131.12 2241.58,2151.45 2253.02,2162.89 2300.4,2162.89 2312.35,2174.84 2312.35,2188.42 2320.6,2196.67 2684.66,2196.67 2710.13,2171.2 2878.53,2171.2 v1(2913.24,2205.91)
  Bottom Layer w5.3: R432.2@2056.51,1810.15 2056.51,1826.67 2063.84,1834 2114.36,1834 2118.22,1837.86 2118.22,1838.28 2122.97,1843.03 v1(2122.97,1846.47)
AM263P_EPWM0_A: J2/J4.11 R46.1 | length 1153.3
  Top Layer w5.3: R46.1@3347.99,1687.24 3347.99,1750.3 v1@3407.86,1810.17
  Bottom Layer w5.3: J2/J4.11@2504.17,2050 2564.82,1989.36 2795.63,1989.36 2891.06,1893.93 3325.41,1893.93 v1(3410.06,1809.27)
AM263P_EPWM0_A_R: R46.2 U1.B2 | length 396.2
  Top Layer w4: 3538.93,1414.29 3562.88,1390.34 3562.88,1367.05 U1.B2@3578.63,1351.3
  Top Layer w5.3: R46.2@3348.42,1641.72 3348.42,1587.04 3363.41,1572.05 3381.17,1572.05 3538.93,1414.29
AM263P_EPWM0_B: J6/J8.59 R47.1 | length 1148.9
  Top Layer w5.3: R47.1@3303.11,1687.17 3303.11,1729.93 3435.86,1862.69 3805.98,1862.69 3910.48,1967.18 3910.48,2032.84 3926.33,2048.69 4024.01,2048.69 4066.36,2091.04 4163.14,2091.04 J6/J8.59@4204.17,2050
AM263P_EPWM0_B_R: R47.2 U1.B1 | length 419.9
  Top Layer w4: 3515.26,1382.42 3516.01,1382.42 U1.B1@3547.13,1351.3
  Top Layer w5.3: R47.2@3303.11,1639.93 3303.11,1572.56 3323.1,1552.57 3373.87,1552.57 3506.5,1419.93 3506.5,1391.18 3515.26,1382.42
AM263P_EPWM1_A: J2/J4.37 R48.1 | length 1820.9
  Top Layer w5.3: v1(3377.87,1637.38) 3377.87,1747.78 3383,1752.91 v1(3383,1756.35)
  Bottom Layer w5.3: J2/J4.37@1904.17,1950 1948.04,1906.14 2568.11,1906.14 2636.76,1974.78 2795.21,1974.78 2886.67,1883.33 3293.67,1883.33 3383,1794 v1(3383,1756.35) ; R48.1@3373.91,1577.15 3377.87,1581.11 v1(3377.87,1637.38)
AM263P_EPWM1_A_R: R48.2 U1.D3 | length 413.8
  Top Layer w10: v1(3594.38,1304.06) U1.D3@3610.13,1288.31
  SIG 1 w4: v1(3376.47,1490.47) 3462.55,1490.47 3486.2,1466.82 3486.2,1380.22 3562.36,1304.06 v1(3594.38,1304.06)
  Bottom Layer w5.3: R48.2@3373.91,1533.84 3376.83,1530.93 v1@3376.83,1489.38
AM263P_EPWM1_B: J2/J4.38 R49.1 | length 2036.6
  Top Layer w5.3: R49.1@3283.41,1410.1 3283.41,1411.05 3276.12,1418.34 3275.16,1418.34 3247.06,1446.45 3247.06,1758.17 v1(3293.79,1804.9)
  Bottom Layer w5.3: J2/J4.38@1804.17,1950 1858.96,1895.21 2572.18,1895.21 2641.15,1964.18 2784.11,1964.18 2875.57,1872.73 3225.96,1872.73 v1(3293.79,1804.9)
AM263P_EPWM1_B_R: R49.2 U1.D2 | length 293
  Top Layer w4: 3515.64,1305.38 3561.56,1305.38 U1.D2@3578.63,1288.31
  Top Layer w5.3: R49.2@3345.34,1409.63 3346.1,1410.39 3416.8,1410.39 3426.72,1400.47 3426.72,1385.69 3431.15,1381.26 3431.15,1380.9 3506.67,1305.38 3515.64,1305.38
AM263P_EPWM2_A: J2/J4.39 R50.1 | length 2138.2
  Top Layer w5.3: R50.1@3292.62,1515.62 3288.62,1519.62 3288.62,1547.81 3272.65,1563.78 3272.65,1714.54 3306.37,1748.26 3306.37,1777.37 v1(3338.27,1809.27)
  Bottom Layer w5.3: J2/J4.39@1704.17,1950 1706.96,1950 1774.19,1882.77 2176.41,1882.77 2219.63,1839.55 2221.17,1838.02 2223.33,1838 2282.08,1837.44 2284.3,1837.44 2325.4,1878.54 2570.5,1878.54 2645.54,1953.58 2772.57,1953.58 2931.96,1794.19 3269.36,1794.19 3279.32,1784.23 3313.22,1784.23 v1(3338.27,1809.27)
AM263P_EPWM2_A_R: R50.2 U1.C2 | length 334.9
  Top Layer w4: 3529.96,1345.78 3540.19,1335.55 3562.88,1335.55 U1.C2@3578.63,1319.8
  Top Layer w5.3: R50.2@3344.01,1519.96 3349.43,1514.54 3390.78,1514.54 3486.25,1419.07 3486.25,1396.25 3529.96,1352.54 3529.96,1345.78
AM263P_EPWM2_B: J2/J4.40 R51.1 | length 2191.6
  Top Layer w5.3: v1@3285.67,1751.24 3285.17,1751.24 3282.13,1748.2 3282.13,1747.7 3257.66,1723.23 3257.66,1472.63 3260.76,1469.53 R51.1@3291.14,1469.53
  Bottom Layer w5.3: J2/J4.40@1604.17,1950 1649.13,1905.04 1735.58,1905.04 1768.45,1872.17 2158.57,1872.17 2212.62,1818.12 2285.61,1818.12 2335.43,1867.94 2574.89,1867.94 2649.93,1942.98 2768.18,1942.98 2927.57,1783.59 3259.6,1783.59 3274.69,1768.5 v1(3286.84,1756.35)
AM263P_EPWM2_B_R: R51.2 U1.C1 | length 286
  Top Layer w5.3: R51.2@3336.88,1469.02 3398.5,1469.02 3465.77,1401.75 3465.77,1377.91 3523.87,1319.8 U1.C1@3547.13,1319.8
AM263P_EPWM3_A: J6/J8.77 R52.1 | length 2097.1
  Top Layer w5.3: R52.1@3289.68,1316.91 3280.52,1326.07 3273.27,1326.07 3259.11,1340.23 3259.11,1378.75 3225.68,1412.17 3225.68,1779.4 3330.17,1883.89 3718.55,1883.89 3761.17,1926.51 3761.17,2075 3860.61,2174.44 4319.4,2174.44 4356.72,2137.13 4356.72,1997.46 J6/J8.77@4404.17,1950
AM263P_EPWM3_A_R: R52.2 U1.E2 | length 266.6
  Top Layer w4: 3515.64,1272.56 3562.88,1272.56 U1.E2@3578.63,1256.81
  Top Layer w5.3: R52.2@3336.92,1316.91 3338.39,1315.44 3459.09,1315.44 3501.97,1272.56 3515.64,1272.56
AM263P_EPWM3_B: J6/J8.78 R53.1 | length 1605.2
  Bottom Layer w5.3: R53.1@3055.32,1341.34 3055.32,1367.06 3119.43,1431.17 3119.43,1439.67 3147.88,1468.12 3211.15,1468.12 3327.57,1584.54 3327.57,1653.22 3358.05,1683.71 3499.45,1683.71 3570.48,1754.74 3570.48,1783.55 3647.05,1860.12 3854.47,1860.12 3865.8,1871.46 3929.38,1871.46 3955.93,1844.91 4034.02,1844.91 4075.53,1886.42 4092.61,1886.42 4098.73,1880.3 4234.47,1880.3 J6/J8.78@4304.17,1950
AM263P_EPWM3_B_R: R53.2 U1.E3 | length 563.6
  Top Layer w10: v1(3594.38,1272.56) U1.E3@3610.13,1256.81
  SIG 1 w4: 3523,1272.56 v1(3594.38,1272.56)
  SIG 1 w4.75: v1(3106.04,1308.64) 3106.46,1308.22 3226,1308.22 3267.22,1267 3518,1267 3523,1272
  Bottom Layer w5.3: R53.2@3094.69,1336.34 3096.87,1336.34 3106.04,1327.18 v1(3106.04,1308.64)
AM263P_EPWM4_A: J6/J8.52 R433.1 | length 2359.5
  Top Layer w5.3: 3242.84,1781.56 3236.28,1775.01 3236.28,1416.56 3269.71,1383.14 3269.71,1379.88 3285.25,1364.34 R433.1@3289.18,1364.34 ; 3243.5,1782.22 3334.56,1873.29 3801.59,1873.29 3899.52,1971.22 3899.52,2094.24 3941.83,2136.55 4250.78,2136.55 v1(4273.66,2113.67)
  Bottom Layer w5.3: v1(4273.66,2113.67) 4840.5,2113.67 J6/J8.52@4904.17,2050
AM263P_EPWM7_B: J6/J8.51 R436.1 | length 2858.9
  Top Layer w5.3: v1(3127.18,1359.13) 3126.58,1306.53 3126.58,1302.14 3160.26,1268.46 3160.26,1263.29 3170.43,1253.12 3259.86,1253.12 3272.14,1240.83 3280.91,1240.83 R436.1@3290.61,1231.13 ; v1(3138.95,1431.58) 3150.74,1443.36 3150.74,1809.39 3350.4,2009.05 3350.4,2074.89 3480.32,2204.81 4455.44,2204.81 4475.33,2184.91 v1(4475.33,2143.82)
  SIG 1 w5.3: v1@3127.03,1356.69 3138.95,1368.61 v1(3138.95,1431.58)
  Bottom Layer w5.3: v1(4475.33,2143.82) 4909.82,2143.82 ; 4910.35,2143.82 J6/J8.51@5003.54,2050.64 ; J6/J8.51@5003.91,2050.26 J6/J8.51@5004.17,2050
AM263P_EPWM7_B_R: R436.2 U1.F1 | length 203.5
  Top Layer w5.3: R436.2@3341.77,1231.15 3477.47,1231.15 3483.99,1224.63 U1.F1@3542.6,1224.63
AM263P_EPWM9_A: J6/J8.75 R9.1 | length 2520.8
  Top Layer w5.3: R9.1@3073.65,1248.26 3073.65,1348.2 3114.71,1389.25 3125.59,1389.25 3161.34,1425 3161.34,1804.99 3361,2004.66 3361,2070.5 3481.78,2191.28 4445.73,2191.28 4461.73,2175.28 4461.73,2157.83 4455.81,2151.91 4455.81,2113.92 4459.46,2110.27 4459.46,2110.02 4460.2,2109.27 4460.2,1935.94 4487.17,1908.96 4563.14,1908.96 J6/J8.75@4604.17,1950
AM263P_EPWM9_A_R: R9.2 U1.G1 | length 460.4
  Top Layer w4: 3515.64,1193.82 U1.G1@3547.13,1193.82
  Top Layer w5.3: R9.2@3120.89,1248.26 3124.83,1248.26 3163.69,1209.4 3251.99,1209.4 3269.51,1191.88 3376.97,1191.88 3391.03,1205.95 3461.92,1205.95 3474.05,1193.82 3515.64,1193.82
AM263P_EPWM9_B: J6/J8.76 R12.1 | length 2596.5
  Top Layer w5.3: R12.1@3051.15,1135.05 3047.21,1135.05 3038.05,1144.21 3038.05,1330.44 3119.18,1411.57 3119.18,1412.19 3119.43,1412.43 3119.43,1439.67 3130.86,1451.11 3131.03,1451.11 3140.14,1460.22 3140.14,1813.78 3339.8,2013.44 3339.8,2079.28 3480.31,2219.79 4480.96,2219.79 4553.32,2147.43 4553.32,1999.15 J6/J8.76@4504.17,1950
AM263P_EPWM9_B_R: R12.2 U1.J2 | length 500.8
  Top Layer w4: 3515.64,1144.7 3564.76,1144.7 U1.J2@3578.63,1130.83
  Top Layer w5.3: R12.2@3098.4,1135.05 3118.95,1135.05 3131.99,1122 3185.18,1122 3193.51,1130.34 3320.38,1130.34 3329.02,1138.98 3329.57,1138.98 3332.02,1141.43 3496.43,1141.43 3499.7,1144.7 3515.64,1144.7
AM263P_EPWM12_A: J6/J8.53 R280.1 | length 2928.4
  Top Layer w5.3: R280.1@3049.29,1017.58 3023.7,1017.58 3001.13,1040.15 3001.13,1106.86 3025.35,1131.09 3025.35,1333.35 3108.83,1416.82 3108.83,1444.06 3129.35,1464.58 3129.35,1582.91 ; 3129.54,1582.91 3129.54,1819.46 3329.2,2019.12 3329.2,2085.2 3481.66,2237.66 4743.07,2237.66 4804.17,2176.55 J6/J8.53@4804.17,2050
AM263P_EPWM12_A_R: R280.2 U1.K2 | length 526.8
  Top Layer w4: 3515.64,1116.95 3561.01,1116.95 U1.K2@3578.63,1099.33
  Top Layer w5.3: R280.2@3100.47,1017.58 3153.11,1070.22 3165.45,1070.22 3165.64,1070.41 3225.33,1070.41 3249.85,1094.93 3250.4,1094.93 3264.61,1109.14 3329.71,1109.14 3337.7,1117.13 3512.82,1117.13 3512.99,1116.95 3515.64,1116.95
AM263P_EPWM12_B: J6/J8.57 R281.1 | length 1869.1
  Bottom Layer w5.3: R281.1@3037.12,1269.75 3020.86,1286.01 3020.86,1347.59 3108.83,1435.56 3108.83,1444.06 3143.49,1478.72 3205.72,1478.72 3316.97,1589.96 3316.97,1657.61 3353.66,1694.31 3495.06,1694.31 3559.88,1759.13 3559.88,1787.94 3642.66,1870.72 3841.76,1870.72 3853.09,1882.06 3933.77,1882.06 3939.13,1876.69 3987.7,1876.69 4009.38,1898.36 4095.89,1898.36 4103.35,1890.9 4222.75,1890.9 4254.82,1922.98 4254.82,1970 4284.82,2000 4354.17,2000 J6/J8.57@4404.17,2050 ; R281.1@3037.15,1269.75 R281.1@3044.58,1262.32
AM263P_EPWM12_B_R: R281.2 U1.J4 | length 623.1
  Top Layer w10: v1(3625.87,1146.57) U1.J4@3641.62,1130.83
  SIG 1 w4: 3578.32,1162.63 3609.82,1162.63 v1(3625.87,1146.57)
  SIG 1 w4.75: v1(3099.4,1215.66) 3152.36,1215.66 3157.66,1210.36 3497.79,1210.36 3545.53,1162.63 3578.32,1162.63
  Bottom Layer w5.3: R281.2@3097.49,1260.59 3099.4,1258.68 v1(3099.4,1215.66)
AM263P_EPWM13_A: J6/J8.79 R59.1 | length 1694.6
  Bottom Layer w5.3: R59.1@3048,1181.51 3038.84,1190.67 3038.84,1197.17 3010.26,1225.75 3010.26,1351.98 3098.23,1439.95 3098.23,1448.45 3139.1,1489.32 3201.33,1489.32 3306.37,1594.35 3306.37,1662.01 3349.27,1704.91 3490.67,1704.91 3549.28,1763.52 3549.28,1792.33 3642.63,1885.68 3831.89,1885.68 3842.6,1896.4 3943.72,1896.4 3950.24,1889.88 3985.9,1889.88 4004.98,1908.96 4163.14,1908.96 J6/J8.79@4204.17,1950
AM263P_EPWM13_A_R: R59.2 U1.K4 | length 602.9
  Top Layer w10: v1(3625.87,1083.58) U1.K4@3641.62,1099.33
  SIG 1 w4.75: v1(3131.58,1155.59) 3128.48,1155.59 3130.03,1154.04 3151.19,1132.88 3182.23,1132.88 3185.4,1136.05 3515.64,1136.05 3573.4,1136.05 3575.85,1133.61 v1(3625.87,1083.58)
  Bottom Layer w5.3: R59.2@3094.69,1181.51 3102.56,1181.51 3128.48,1155.59 v1(3131.58,1155.59)
AM263P_EPWM13_B: J6/J8.80 R60.1 | length 1676.5
  Bottom Layer w5.3: R60.1@3056.12,1135.05 3051.06,1140.11 3033.56,1140.11 3025.58,1148.09 3025.58,1183.4 2999.66,1209.32 2999.66,1356.38 3087.63,1444.34 3087.63,1452.84 3134.71,1499.92 3196.94,1499.92 3295.77,1598.74 3295.77,1666.4 3344.88,1715.51 3486.28,1715.51 3538.68,1767.91 3538.68,1796.72 3638.24,1896.28 3827.49,1896.28 3843.32,1912.1 3943.01,1912.1 3954.63,1900.48 3981.51,1900.48 4031.03,1950 J6/J8.80@4104.17,1950
AM263P_EPWM13_B_R: R60.2 U1.K3 | length 563.3
  Top Layer w10: v1(3594.38,1083.58) U1.K3@3610.13,1099.33
  SIG 1 w4.75: v1(3114.94,1106.36) 3169.92,1106.36 3189.56,1126 3515.64,1126 3551.96,1126 3579.87,1098.09 v1(3594.38,1083.58)
  Bottom Layer w5.3: R60.2@3097.46,1135.05 3102.15,1130.36 3102.15,1119.15 v1(3114.94,1106.36)
AM263P_EPWM14_A: J2/J4.35 R282.1 | length 4081.3
  Top Layer w5.3: J2/J4.35@2104.17,1950 2074.62,1920.45 2074.62,1846.32 1994.67,1766.37 1994.67,1531.6 2003.88,1522.4 2003.88,1478.04 2079.98,1401.94 2120.34,1401.94 v1(2141.83,1380.45) ; v1(4125,459.85) 4125,604.67 4143,622.67 R282.1@4143,651.06 ; R282.1@4141.03,653.03 R282.1@4143,655
  Bottom Layer w5.3: v1(2141.83,1380.45) v1(2141.83,1380.45) 2125,1363.69 2125,1190.1 2109.83,1174.93 2109.83,733.1 2160.62,682.31 2217.09,682.31 2251.04,648.37 2267.21,648.37 2358.7,739.86 2358.7,777.37 2440.56,859.22 2615.5,859.22 2689.43,785.29 2833.01,785.29 2849.73,768.57 2857.72,768.57 2885.15,741.15 2885.15,622.6 2967.69,540.06 3331.43,540.06 3397.72,473.77 3397.72,423.25 3428.79,392.18 3495.16,392.18 3514.87,372.48 3776.04,372.48 3804.11,344.4 3937.93,344.4 4052.51,458.99 4124.13,458.99 v1(4125,459.85)
AM263P_EPWM14_A_R: R282.2 U1.V17 | length 204.1
  Top Layer w5.3: U1.V17@4051.07,847.36 4051.07,763.99 4120.69,694.37 R282.2@4143,694.37
AM263P_EPWM14_B: J2/J4.36 R283.1 | length 4183.7
  Top Layer w5.3: J2/J4.36@2004.17,1950 1993.83,1939.66 1993.83,1797.86 1971.59,1775.63 1971.59,1539.69 1993.28,1518.01 1993.28,1473.65 2075.59,1391.34 2088.21,1391.34 v1(2106.62,1372.93)
  Bottom Layer w5.3: v1(2106.62,1372.93) 2106.62,1371.24 2114.4,1363.47 2114.4,1194.49 2099.23,1179.32 2099.23,728.71 2156.22,671.71 2156.83,671.71 2157.32,671.23 2213.19,671.23 2246.65,637.77 2271.6,637.77 2319.57,685.74 2348.74,685.74 2431.73,768.73 2431.73,832.09 2446.46,846.83 2612.91,846.83 2686.59,773.15 2821.31,773.15 2839.16,755.3 2839.16,731.91 2874.55,696.52 2874.55,618.2 3039.67,453.08 3217.35,453.08 3228.88,441.55 3259,441.55 3275.23,457.77 3375.19,457.77 3387.12,445.84 3387.12,418.86 3424.4,381.58 3490.77,381.58 3510.48,361.88 3771.65,361.88 3799.72,333.8 3942.32,333.8 4038.52,430 4123.63,430 4134.23,440.6 4165.66,440.6 4276.55,551.5 4278.1,594.96 ccw(c4258.67,596.82) 4278.19,597.04 4235.53,639.7 R283.1@4195.58,639.7
AM263P_EPWM14_B_R: R283.2 U1.T16 | length 321.7
  Top Layer w10: U1.T16@4019.57,910.35 v1(4035.32,894.61)
  SIG 1 w4.75: v1(4035.32,894.61) 4081.83,894.61 4190,786.43 v1(4190,724.36)
  Bottom Layer w4.75: v1@4192.03,723.35 4192.03,718.75 4195.58,715.19 R283.2@4195.58,686.94
AM263P_EPWM15_A: R284.1 U54.4 | length 2245.9
  Top Layer w5.3: U54.4@2554,681.41 2554,709.92 2558.64,714.57 v1(2558.64,718.01)
  Bottom Layer w5.3: v1(2558.64,718.01) 2598.51,757.87 2654.05,757.87 2670.73,741.18 2759.95,741.18 2835.24,665.89 2835.24,607.11 3021.07,421.28 3202.73,421.28 3218.48,405.53 3218.6,405.53 3274.35,349.78 3477.6,349.78 3497.3,330.08 3696.8,330.08 3697.02,329.85 3758.7,329.85 3788.93,299.62 3968.81,299.62 3981.75,312.55 4023.09,312.55 4058,347.46 4058,366.93 4085.72,394.65 4158.13,394.65 4178.22,414.74 4178.22,438.18 4287.15,547.11 4288.7,548.66 4288.79,596.76 ccw(c4258.67,596.82) 4288.79,597.07 4288.7,609.21 4287.15,610.76 4283.14,614.77 R284.1@4283.14,654.64
AM263P_EPWM15_A_BP: J2/J4.34 U54.3 | length 3020.6
  Top Layer w5.3: v1(2202.56,1340.16) 2161.35,1381.37 2161.35,1388.54 2137.35,1412.54 2084.37,1412.54 2014.48,1482.43 2014.48,1511.23 2033.72,1530.48 2033.72,1613.06 2023.5,1623.28 2023.5,1778.33 2085.22,1840.06 2085.22,1851.32 2129.23,1895.33 2149.5,1895.33 J2/J4.34@2204.17,1950 ; U54.3@2579.59,681.41 2579.59,697.65 2598.97,717.04 2598.97,727.25 v1(2600.42,728.69)
  SIG 1 w4.75: v1(2202.56,1340.16) 2238.16,1375.76 2251.18,1375.76 2258.79,1368.15 2311.86,1368.15 2383.32,1439.61 2447.08,1439.61 2472.42,1414.27 2472.42,1249.49 2348.3,1125.37 2348.3,935.59 2332.34,919.63 2290.88,919.63 2162.26,1048.26 2044.3,1048.26 2006.22,1010.18 2006.22,983.52 2083.51,906.24 2083.51,771 2134.64,719.87 2400.88,719.87 2441.24,679.51 2463.31,679.51 2542.61,758.81 2568.42,758.81 2598.54,728.69 v1(2600.42,728.69)
AM263P_EPWM15_A_R: R284.2 U1.P15 | length 611.6
  Top Layer w10: U1.P15@3988.08,973.35 v1(4003.83,957.6)
  SIG 1 w4: v1(4003.83,957.6) 4018.83,972.6 4041.54,972.6
  SIG 1 w4.75: 4041.8,972.86 4255.88,972.86 4314.45,914.29 4314.45,777.05 v1(4264.2,726.8)
  Bottom Layer w5.3: v1(4264.2,726.8) 4266.63,724.37 4266.63,718.54 4282.93,702.24 R284.2@4282.93,694.37
AM263P_EPWM15_B: R285.1 U54.7 | length 3005.9
  Top Layer w5.3: U54.7@2477.23,681.41 2477.23,697.16 2538.88,758.81 2735.45,758.81 2808.71,685.56 2898.09,685.56 2999.55,787.02 3066.87,787.02 3082.49,771.39 3082.49,695.98 3143.93,634.53 3143.93,478.25 3133.45,467.77 3133.45,346.61 3155.63,324.43 3276.55,324.43 3304.62,296.36 3304.62,240.26 3325.74,219.14 3325.74,104.04 3365.93,63.85 3568.5,63.85 3596.95,92.3 3711.79,92.3 3740.24,63.85 3993.82,63.85 4025.37,95.4 4025.37,239.45 4057.5,271.57 4057.5,404.01 4072.19,418.7 4120.02,418.7 4173.1,471.79 4173.1,589.33 4226.22,642.44 R285.1@4226.22,646.38 ; R285.1@4227.03,637.96 4227.31,637.96 4235.48,646.14 R285.1@4235.48,652.05
AM263P_EPWM15_B_BP: J5/J7.45 U54.6 | length 2997.8
  Top Layer w5.3: U54.6@2502.82,681.41 2504.82,683.41 2504.82,706.02 2531.13,732.34 2547.01,748.21 2697.73,748.21 2720.3,725.64 2720.3,723.92 2720.55,723.67 2720.55,702.97 2754.69,668.83 2896.81,668.83 3004.4,776.42 3062.48,776.42 3071.89,767 3071.89,691.59 3133.33,630.14 3133.33,482.64 3122.85,472.16 3122.85,342.22 3151.24,313.83 3267.82,313.83 3294.02,287.63 3294.02,228.21 3315.14,207.08 3315.14,95.39 3357.28,53.25 4116.06,53.25 4141.97,79.16 4141.97,101.56 4120.57,122.96 4120.57,178.87 4159.42,217.72 4159.42,269.23 4185.07,294.88 4459.3,294.88 J5/J7.45@4504.17,250
AM263P_EPWM15_B_R: R285.2 U1.R16 | length 402.2
  Top Layer w4.75: R285.2@4226.22,693.62 4226.22,719.42 v1(4228.56,721.75)
  Top Layer w10: U1.R16@4019.57,941.85 v1(4035.32,926.1)
  SIG 1 w4.75: v1(4035.32,926.1) 4037.75,923.67 4151.15,923.67 4228.56,846.27 v1(4228.56,721.75)
AM263P_EQEP0_A: R328.1 U1.B14 | length 3929
  Top Layer w5.3: U1.B14@3956.58,1351.3 3973.55,1368.27 3973.55,1414.29 3973.55,1442.96 4034.3,1503.71 4034.3,1688.64 4125.91,1780.25 4141.38,1780.25 4181.91,1820.78 4745.73,1820.78 4776.05,1851.09 5040.05,1851.09 5054.73,1865.78 5236.97,1865.78 5240.75,1869.56 v1(5272.28,1869.56)
  Bottom Layer w5.3: v1(5272.28,1869.56) 5237.01,1904.82 5169.07,1904.82 5074.53,1810.29 5074.53,1704.97 5191.17,1588.33 5191.17,1341.71 5228.38,1304.5 5228.38,1230 5301.68,1156.71 5301.68,867.97 5228.7,795 5228.7,750 5179.61,700.9 5179.61,569.24 5179.37,569.01 5179.37,552.94 5149.33,522.9 5149.33,159.5 5233.84,75 R328.1@5301.38,75
AM263P_EQEP0_A_R: R328.2 U43.1 | length 277.2
  Bottom Layer w5.3: R328.2@5348.62,75 5524.13,75 5574.13,125 U43.1@5574.13,155.98
AM263P_EQEP0_B: R329.1 U1.A14 | length 3673.7
  Top Layer w5.3: U1.A14@3956.58,1382.8 3956.85,1383.06 3956.85,1396.15 3962.95,1402.25 3962.95,1414.29 3962.95,1447.35 4023.7,1508.1 4023.7,1693.03 4121.52,1790.85 4136.99,1790.85 4170.25,1824.11 4173.45,1827.3 4177.52,1831.38 4740.06,1831.38 4770.38,1861.69 5035.66,1861.69 5059.26,1885.3 v1(5228.38,1885.3)
  Bottom Layer w5.3: v1(5228.38,1885.3) 5196.33,1853.25 5153.42,1853.25 5141.98,1841.81 5141.98,1652.51 5201.77,1592.72 5201.77,1354.98 5279.52,1277.22 5279.52,1226.22 5312.28,1193.47 5312.28,838.75 5268.53,795 5268.53,752.23 5190.21,673.91 5190.21,550.62 5189.97,550.39 5189.97,548.55 5159.93,518.51 5159.93,194.63 5219.47,135.09 R329.1@5301.38,135.09
AM263P_EQEP0_B_R: R329.2 U43.3 | length 213.4
  Bottom Layer w5.3: R329.2@5348.62,135.09 5399.09,135.09 5443.62,179.63 5454.74,179.63 5466.52,191.41 U43.3@5538.7,191.41
AM263P_EQEP0_INDEX: R330.1 U1.D11 | length 3580.2
  Top Layer w10: U1.D11@3862.09,1288.31 v1(3877.84,1304.06)
  SIG 1 w4: v1(3877.84,1304.06) 3894.34,1320.55 3894.34,1343.12 3910.09,1358.87 3910.09,1414.29
  SIG 1 w4.75: 3910.09,1414.29 3910.09,1501.49 3901.4,1510.18 3901.4,1598.41 3953.46,1650.48 3953.46,1744.32 3915.15,1782.62 3915.15,1924.95 3950.58,1960.37 3983.18,1960.37 4008.38,1935.18 4008.38,1914.75 4042.4,1880.73 4042.4,1868.7 4042.4,1825 4158.86,1708.55 4228.8,1708.55 4239.67,1697.68 4296.89,1697.68 4487.65,1506.92 4538.36,1506.92 4635.28,1410 4654.74,1410 4679.81,1384.94 4679.81,1347.98 4738.38,1289.4 4945.95,1289.4 4975.26,1318.71 5047.28,1318.71 5092.57,1364 5268.8,1364 v1(5269.14,1364.34)
  Bottom Layer w5.3: R330.1@5229.44,397.13 5229.44,421.97 5289.73,482.26 5289.73,611.02 5359.88,681.17 5359.88,860.04 5382.23,882.4 5412.4,882.4 5435,905 5435,1084.57 5413.5,1106.07 5413.5,1165.36 5382.23,1196.63 5382.23,1222.76 5269.65,1335.35 5269.65,1363.83 v1(5269.14,1364.34)
AM263P_EQEP0_INDEX_R: R330.2 U43.4 | length 447
  Bottom Layer w5.3: R330.2@5229.44,349.89 5229.44,323.53 5251.92,301.05 5251.92,219.93 5281.63,190.23 5450.35,190.23 5471.22,211.1 U43.4@5538.7,211.1
AM263P_EQEP0_STROBE: R331.1 U1.C12 | length 3543.1
  Top Layer w10: U1.C12@3893.59,1319.8 v1(3909.34,1335.55)
  SIG 1 w4: v1(3909.34,1335.55) 3925.83,1352.05 3925.83,1414.29
  SIG 1 w4.75: 3925.83,1414.29 3925.83,1499.95 3911.45,1514.34 3911.45,1594.25 3963.51,1646.32 3963.51,1748.48 3925.2,1786.79 3925.2,1920.79 3954.74,1950.32 3979.01,1950.32 3998.32,1931.01 3998.32,1910.59 4032.35,1876.57 4032.35,1864.54 4032.35,1819.53 4048.13,1803.76 4048.13,1793.85 4143.48,1698.5 4222.99,1698.5 4233.86,1687.63 4292.73,1687.63 4484.49,1495.87 4531.12,1495.87 4610.15,1416.84 4610.15,1399.73 4730.52,1279.35 4950.12,1279.35 4979.43,1308.66 5051.44,1308.66 5085.28,1342.5 5297.17,1342.5 v1(5299.19,1344.52)
  Bottom Layer w5.3: R331.1@5277.45,397.13 5277.45,442.72 5304.1,469.37 5304.1,610.4 5370.48,676.78 5370.48,815.42 5465.38,910.33 5465.38,1229.97 5405.35,1290 5338.92,1290 5301.27,1327.65 5301.27,1342.45 v1(5299.19,1344.52)
AM263P_EQEP0_STROBE_R: R331.2 U43.5 | length 389.8
  Bottom Layer w5.3: R331.2@5277.45,349.89 5277.45,331.1 5303.54,305 5330,305 5351.33,283.67 5351.33,209.7 5360.2,200.83 5445.96,200.83 5475.91,230.78 U43.5@5538.7,230.78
